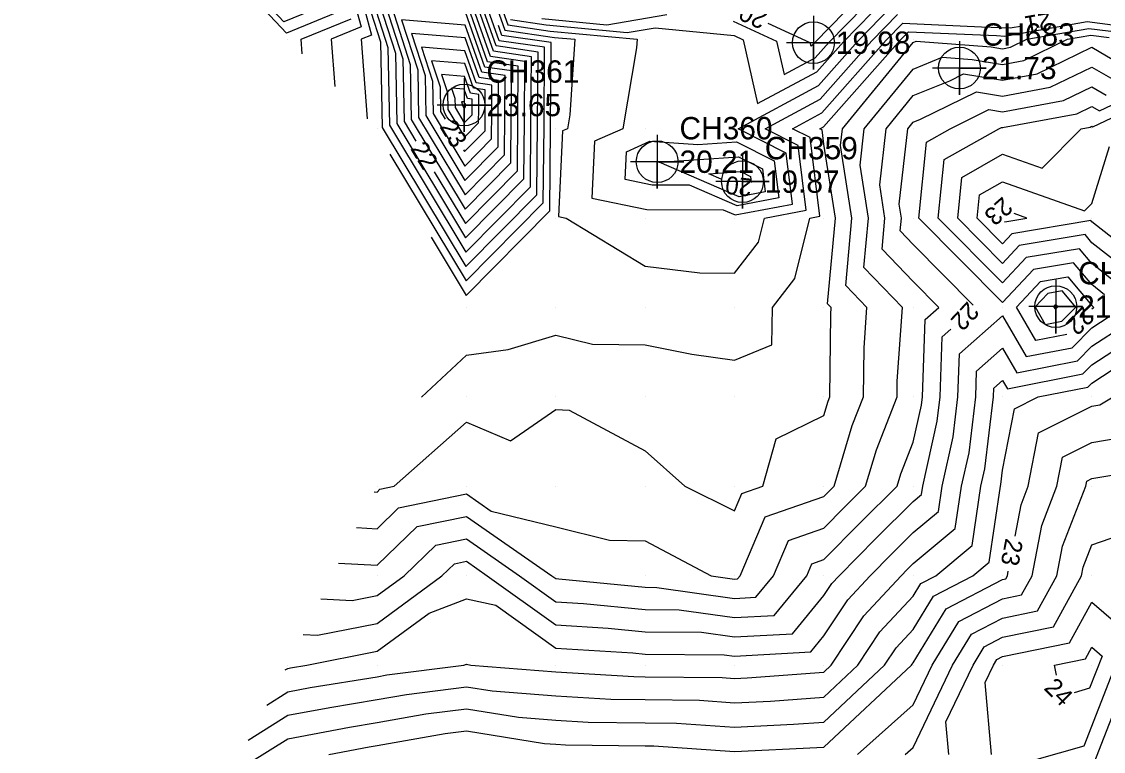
# Model space of a CAD drawing. Extents: x 2531902 to 2533249, y 715219 to 716099.
# Drawn here: x 2532680.2 to 2532801.3, y 715530.4 to 715612 of the extents above; entities that cross this region are included whole.
import ezdxf

# ---------------------------------------------------------------- set-up
doc = ezdxf.new("R2010")
doc.units = 0
for name, color, linetype in [('DTM Contours Major', 7, 'Continuous'), ('DTM Contours Major Text', 7, 'Continuous'), ('DTM Contours Minor', 7, 'Continuous'), ('Exist DTM QL2 LIDAR Elevation Point', 7, 'Continuous'), ('Exist DTM Regular Point CELL', 7, 'Continuous'), ('Exist DTM Regular Point Cogo Elevation', 7, 'Continuous'), ('Exist DTM Regular Point Cogo Number', 7, 'Continuous')]:
    doc.layers.add(name, color=color, linetype=linetype)

msp = doc.modelspace()

# ---------------------------------------------------------------- linework, layer by layer
at = {"layer": 'DTM Contours Major'}
for points in [[(2532732.26, 715615.31), (2532730.81, 715619.4), (2532730.83, 715620.41), (2532728.37, 715621.29), (2532719.99, 715622.47), (2532714.91, 715622.89), (2532715.92, 715619.72), (2532718.24, 715611.38), (2532714.85, 715610), (2532715.26, 715604.74)], [(2532763.74, 715611.81), (2532768.45, 715609.64), (2532768.53, 715609.28), (2532768.86, 715609.46), (2532769, 715609.63), (2532775.8, 715616.6), (2532779.22, 715616.44), (2532793.91, 715615.79), (2532798.21, 715616.54), (2532800.2, 715616.3), (2532801.37, 715617.07)], [(2532732.38, 715607.49), (2532729.92, 715614.46), (2532720.51, 715615.24), (2532722.88, 715607.82), (2532723.02, 715600.82), (2532724.35, 715598.61)], [(2532724.99, 715569.97), (2532730, 715574.66), (2532734.69, 715575.31), (2532740, 715576.89), (2532744.11, 715575.89), (2532750, 715575.81), (2532755.22, 715574.78), (2532760, 715574.1), (2532764.18, 715575.82), (2532764.27, 715580), (2532766.77, 715583.23), (2532768.45, 715590), (2532769.54, 715590.21), (2532768.47, 715599), (2532766.5, 715600), (2532769.79, 715601.76), (2532776.99, 715609.9), (2532778.85, 715611.81), (2532787.64, 715611.41), (2532790.86, 715611.27), (2532792.22, 715611.51)], [(2532726.07, 715587.86), (2532729.98, 715581.36), (2532739.34, 715590.82), (2532739.42, 715600.15), (2532739.49, 715609.63), (2532733.98, 715610.43), (2532733.59, 715611.54)], [(2532791.4, 715554.44), (2532792.07, 715557.93), (2532792.87, 715560), (2532794.03, 715565.97), (2532800, 715568.96), (2532800.89, 715569.11), (2532802.4, 715570), (2532808.71, 715572.49), (2532810, 715574.61), (2532812.18, 715570.69), (2532814.07, 715567.41), (2532813.4, 715561.93), (2532816.55, 715570.83), (2532817.98, 715572.95), (2532820.02, 715580.42), (2532822.99, 715583.27), (2532830.28, 715597.71), (2532833.72, 715604), (2532839.45, 715610.25), (2532839.5, 715610.3)], [(2532730.78, 715604.55), (2532729.81, 715607.29), (2532726.11, 715607.6), (2532727.05, 715604.68), (2532727.1, 715601.93), (2532727.62, 715601.06)], [(2532726.41, 715595.18), (2532729.89, 715589.4), (2532735.71, 715595.29), (2532735.77, 715601.09), (2532735.81, 715606.99), (2532732.38, 715607.49)], [(2532786.71, 715580.25), (2532780, 715587.06), (2532778.56, 715588.56), (2532778.69, 715590), (2532778.45, 715591.55), (2532779.4, 715600), (2532780, 715600.73), (2532780.81, 715601.06), (2532787.07, 715604.14), (2532790, 715603.66), (2532795.35, 715604.65), (2532800, 715606.9), (2532802.34, 715605.54)], [(2532729.68, 715597.63), (2532729.8, 715597.44), (2532732.09, 715599.75), (2532732.11, 715602.04), (2532732.12, 715604.36), (2532730.78, 715604.55)], [(2532757.15, 715594.95), (2532760.73, 715595.2), (2532761.79, 715594.66), (2532761.88, 715593.98)], [(2532758.5, 715594.37), (2532757.15, 715594.95)], [(2532790.25, 715589.59), (2532792.73, 715590), (2532791.3, 715590.5)], [(2532790.23, 715589.56), (2532790.25, 715589.59)], [(2532791.55, 715580.03), (2532794.26, 715582.92), (2532797.32, 715583.43), (2532800, 715580.22), (2532800.12, 715580.12), (2532800.23, 715580), (2532800.16, 715579.91), (2532800.01, 715579.82)], [(2532797.19, 715576.98), (2532793.72, 715576.3), (2532791.55, 715580.03)], [(2532711.72, 715543.44), (2532713.35, 715543.35), (2532720, 715544.66), (2532727.27, 715550), (2532728.66, 715551.34), (2532730, 715551.62), (2532732.33, 715550), (2532740, 715544.49), (2532745.86, 715544.14), (2532750, 715543.74), (2532756.33, 715543.67), (2532760, 715543.15), (2532766.48, 715543.52), (2532770, 715547.78), (2532770.88, 715549.12), (2532771.7, 715550), (2532775.82, 715554.18), (2532780, 715558.3), (2532780.93, 715559.07), (2532781.07, 715560), (2532782.7, 715567.3), (2532783.02, 715570), (2532783.26, 715576.74), (2532784.22, 715577.58)], [(2532714.59, 715530), (2532719.13, 715530.87), (2532720, 715531.01), (2532727.64, 715532.36), (2532730, 715532.66), (2532738.76, 715531.24), (2532740, 715531.15), (2532741.08, 715531.08), (2532750, 715530.98), (2532750.97, 715530.97), (2532760, 715530.33), (2532769.23, 715530.77), (2532770, 715530.83), (2532779.8, 715540), (2532779.88, 715540.12), (2532780, 715540.25), (2532783.7, 715546.3), (2532790, 715549.57), (2532790.36, 715549.64), (2532790.55, 715550), (2532790.65, 715550.51)], [(2532799.29, 715540.71), (2532800, 715542.02), (2532801.15, 715541.02), (2532799.74, 715537.41), (2532798, 715536.92)], [(2532796.03, 715538.87), (2532795.82, 715540), (2532799.29, 715540.71)]]:
    msp.add_lwpolyline(points, dxfattribs=at)
at = {"layer": 'DTM Contours Minor'}
for points in [[(2532680.23, 715639.75), (2532680.75, 715639.45), (2532713.17, 715623.21), (2532715.95, 715613.19), (2532709.85, 715610.7), (2532701.16, 715619.94), (2532698.66, 715621.23), (2532689.96, 715621.44), (2532684.17, 715629.76), (2532680.23, 715639.75)], [(2532681.39, 715638.49), (2532684.59, 715636.63), (2532712.42, 715622.69), (2532714.81, 715614.09), (2532709.57, 715611.95), (2532702.11, 715619.88), (2532697.57, 715622.24), (2532689.94, 715622.42), (2532684.85, 715629.72), (2532681.39, 715638.49)], [(2532721.42, 715597.16), (2532729.97, 715582.97), (2532738.61, 715591.71), (2532738.69, 715600.34), (2532738.75, 715609.11), (2532733.66, 715609.84), (2532730.1, 715619.93), (2532730.1, 715620.05), (2532729.81, 715620.15), (2532728.82, 715620.29), (2532716.03, 715621.36), (2532718.58, 715613.38), (2532719.39, 715610.48), (2532718.21, 715610), (2532718.89, 715601.11)], [(2532733.34, 715609.26), (2532729.98, 715618.76), (2532717.15, 715619.83), (2532720.39, 715609.71), (2532720.57, 715600.15), (2532729.95, 715584.58), (2532737.89, 715592.6), (2532737.96, 715600.53), (2532738.02, 715608.58), (2532733.34, 715609.26)], [(2532733.02, 715608.67), (2532729.96, 715617.32), (2532718.27, 715618.3), (2532721.22, 715609.08), (2532721.38, 715600.38), (2532729.93, 715586.18), (2532737.16, 715593.5), (2532737.23, 715600.72), (2532737.28, 715608.05), (2532733.02, 715608.67)], [(2532731.53, 715618.87), (2532734.3, 715611.02), (2532739.86, 715610.21), (2532742.13, 715610), (2532741.57, 715601.57), (2532741.3, 715600), (2532740.75, 715599.75), (2532740.32, 715590.18), (2532741.18, 715590), (2532750, 715584.62), (2532756.11, 715583.89), (2532760, 715583.83), (2532762.69, 715587.31), (2532763.36, 715590), (2532768.01, 715590.89), (2532767.13, 715598.14), (2532763.45, 715600), (2532769.6, 715603.3), (2532775.39, 715609.84), (2532778.24, 715612.76)], [(2532732.24, 715618.34), (2532734.63, 715611.61), (2532739.39, 715610.92), (2532749.1, 715610), (2532749.04, 715609.04), (2532747.49, 715600), (2532744.33, 715598.59), (2532744.05, 715592.25), (2532750.21, 715590.97), (2532758.72, 715590.93), (2532760.08, 715590.35), (2532766.49, 715591.57), (2532765.8, 715597.27), (2532760.4, 715600), (2532769.41, 715604.84), (2532773.79, 715609.79), (2532777.63, 715613.72)], [(2532732.7, 715608.08), (2532729.94, 715615.89), (2532719.39, 715616.77), (2532722.05, 715608.45), (2532722.2, 715600.6), (2532729.91, 715587.79), (2532736.44, 715594.39), (2532736.5, 715600.9), (2532736.54, 715607.52), (2532732.7, 715608.08)], [(2532759.85, 715612.03), (2532764.7, 715609.8), (2532765.56, 715606.05), (2532769.04, 715607.92), (2532770.6, 715609.68), (2532776.41, 715615.64)], [(2532734.95, 715612.2), (2532738.92, 715611.62), (2532748.01, 715610.76), (2532751.13, 715611.29), (2532759.97, 715610.41), (2532760.96, 715609.96), (2532762.58, 715602.81), (2532769.23, 715606.38), (2532772.2, 715609.73), (2532777.02, 715614.68)], [(2532732.06, 715606.9), (2532729.9, 715613.02), (2532721.63, 715613.72), (2532723.72, 715607.19), (2532723.83, 715601.04), (2532729.87, 715591.01), (2532734.99, 715596.18), (2532735.03, 715601.28), (2532735.07, 715606.47), (2532732.06, 715606.9)], [(2532711.62, 715608.38), (2532711.5, 715610), (2532717.1, 715612.29)], [(2532719.68, 715559.37), (2532720, 715559.35), (2532720.33, 715559.67), (2532721.93, 715560), (2532730, 715567.18), (2532734.92, 715565.08), (2532740, 715568.6), (2532741.49, 715568.51), (2532750, 715563.97), (2532754.44, 715560), (2532760, 715557.27), (2532760.82, 715559.18), (2532763.17, 715560), (2532764.67, 715565.33), (2532770, 715567.91), (2532770.48, 715569.52), (2532770.67, 715570), (2532770.78, 715579.22), (2532770.83, 715580), (2532770.42, 715580.42), (2532771.29, 715590), (2532770, 715598.27), (2532769.81, 715599.87), (2532769.56, 715600), (2532769.97, 715600.22), (2532778.59, 715609.95), (2532779.46, 715610.85), (2532789.32, 715610.41), (2532790.25, 715610.36), (2532799.46, 715611.98), (2532803.71, 715611.45)], [(2532731.74, 715606.31), (2532729.87, 715611.59), (2532722.75, 715612.19), (2532724.55, 715606.57), (2532724.65, 715601.26), (2532729.85, 715592.62), (2532734.26, 715597.07), (2532734.3, 715601.47), (2532734.33, 715605.94), (2532731.74, 715606.31)], [(2532738.45, 715612.32), (2532745.73, 715611.63), (2532752.43, 715612.77)], [(2532717.69, 715555.39), (2532720, 715555.26), (2532722.41, 715557.59), (2532730, 715559.16), (2532732.76, 715557.24), (2532740, 715555.46), (2532746.01, 715553.99), (2532750, 715553.92), (2532757.41, 715550), (2532760, 715549.63), (2532760.35, 715549.65), (2532760.63, 715550), (2532763.43, 715556.57), (2532770, 715558.85), (2532770.57, 715559.43), (2532771.15, 715560), (2532773.19, 715566.81), (2532774.43, 715570), (2532774.5, 715575.5), (2532774.82, 715580), (2532772.46, 715582.46), (2532773.14, 715590), (2532771.87, 715598.13), (2532772.08, 715600), (2532780, 715609.66), (2532780.34, 715609.79), (2532788.73, 715609.15), (2532790, 715608.95), (2532790.89, 715609.11), (2532792.72, 715610), (2532799.67, 715611.21), (2532804.29, 715610.65)], [(2532731.42, 715605.73), (2532729.85, 715610.16), (2532723.87, 715610.66), (2532725.38, 715605.94), (2532725.46, 715601.49), (2532729.84, 715594.22), (2532733.54, 715597.97), (2532733.57, 715601.66), (2532733.6, 715605.41), (2532731.42, 715605.73)], [(2532715.7, 715551.4), (2532720, 715551.17), (2532724.5, 715555.5), (2532730, 715556.64), (2532739.56, 715550), (2532740, 715549.68), (2532740.34, 715549.66), (2532750, 715548.72), (2532751.3, 715548.7), (2532760, 715547.47), (2532762.39, 715547.61), (2532764.37, 715550), (2532766.05, 715553.95), (2532770, 715555.32), (2532772.32, 715557.68), (2532774.68, 715560), (2532775.91, 715564.09), (2532778.2, 715570), (2532778.22, 715571.78), (2532778.8, 715580), (2532774.49, 715584.49), (2532774.99, 715590), (2532774.06, 715595.94), (2532774.52, 715600), (2532780, 715606.68), (2532783.24, 715607.99), (2532786.61, 715607.74), (2532790, 715607.18), (2532792.38, 715607.62), (2532797.28, 715610), (2532799.88, 715610.45), (2532801.92, 715610.2)], [(2532713.71, 715547.42), (2532717.23, 715547.23), (2532720, 715547.78), (2532723.03, 715550), (2532726.58, 715553.42), (2532730, 715554.13), (2532735.94, 715550), (2532740, 715547.09), (2532743.1, 715546.9), (2532750, 715546.23), (2532753.82, 715546.18), (2532760, 715545.31), (2532764.44, 715545.56), (2532768.1, 715550), (2532768.67, 715551.33), (2532770, 715551.8), (2532774.07, 715555.93), (2532778.21, 715560), (2532778.62, 715561.38), (2532780, 715564.94), (2532780.93, 715569.07), (2532781.04, 715570), (2532781.34, 715578.66), (2532782.86, 715580), (2532780, 715582.9), (2532776.53, 715586.53), (2532776.84, 715590), (2532776.26, 715593.74), (2532776.96, 715600), (2532780, 715603.71), (2532784.1, 715605.37), (2532785.65, 715606.13), (2532790, 715605.42), (2532793.86, 715606.14), (2532800, 715609.11), (2532803.09, 715607.31)], [(2532731.1, 715605.14), (2532729.83, 715608.72), (2532724.99, 715609.13), (2532726.21, 715605.31), (2532726.28, 715601.71), (2532729.82, 715595.83), (2532732.81, 715598.86), (2532732.84, 715601.85), (2532732.86, 715604.88), (2532731.1, 715605.14)], [(2532730.46, 715603.96), (2532729.79, 715605.86), (2532727.23, 715606.07), (2532727.88, 715604.05), (2532727.91, 715602.15), (2532729.78, 715599.05), (2532731.36, 715600.65), (2532731.38, 715602.22), (2532731.39, 715603.83), (2532730.46, 715603.96)], [(2532730.14, 715603.37), (2532729.77, 715604.42), (2532728.35, 715604.54), (2532728.71, 715603.42), (2532728.73, 715602.37), (2532729.76, 715600.66), (2532730.64, 715601.54), (2532730.65, 715602.41), (2532730.65, 715603.3), (2532730.14, 715603.37)], [(2532801.43, 715581.43), (2532800, 715582.56), (2532797.96, 715585), (2532793.46, 715584.25), (2532790, 715580.56), (2532780.63, 715590), (2532781.49, 715598.51), (2532784.13, 715600), (2532788.48, 715602.14), (2532790, 715601.89), (2532796.84, 715603.16), (2532800, 715604.69), (2532801.59, 715603.77)], [(2532802.74, 715582.74), (2532800, 715584.91), (2532798.61, 715586.58), (2532792.66, 715585.58), (2532790, 715582.75), (2532782.81, 715590), (2532783.46, 715596.54), (2532789.6, 715600), (2532789.9, 715600.15), (2532790, 715600.13), (2532798.32, 715601.68), (2532800, 715602.49), (2532800.84, 715602), (2532807.31, 715605.05)], [(2532804.05, 715584.05), (2532800, 715587.25), (2532799.25, 715588.15), (2532791.86, 715586.92), (2532790, 715584.94), (2532784.98, 715590), (2532785.44, 715594.56), (2532790, 715597.14), (2532794.42, 715595.58), (2532798.8, 715600), (2532799.81, 715600.19), (2532800, 715600.28), (2532800.1, 715600.23), (2532807.91, 715603.92)], [(2532729.82, 715602.79), (2532729.74, 715602.99), (2532729.47, 715603.01), (2532729.54, 715602.8), (2532729.55, 715602.59), (2532729.74, 715602.26), (2532729.91, 715602.43), (2532729.91, 715602.6), (2532729.91, 715602.77), (2532729.82, 715602.79)], [(2532760.22, 715598.55), (2532764.46, 715596.4), (2532764.97, 715592.26), (2532760.3, 715591.36), (2532754.96, 715593.68), (2532750.79, 715593.7), (2532747.77, 715594.32), (2532747.91, 715597.43), (2532750.52, 715598.59), (2532755.89, 715598.25), (2532760.22, 715598.55)], [(2532805.36, 715585.36), (2532800, 715589.6), (2532799.89, 715589.73), (2532791.05, 715588.25), (2532790, 715587.13), (2532787.15, 715590), (2532787.41, 715592.59), (2532790, 715594.05), (2532799.18, 715590.82), (2532800, 715591.64), (2532801.98, 715598.02)], [(2532751.57, 715596.26), (2532760.47, 715596.87), (2532763.13, 715595.53), (2532763.44, 715592.94), (2532760.52, 715592.38), (2532751.57, 715596.26)], [(2532798.19, 715580.04), (2532796.68, 715581.85), (2532795.07, 715581.58), (2532793.64, 715580.06), (2532794.78, 715578.1), (2532796.62, 715578.46), (2532798.19, 715580.04)], [(2532796.19, 715580.09), (2532796.04, 715580.28), (2532795.87, 715580.25), (2532795.72, 715580.1), (2532795.84, 715579.89), (2532796.03, 715579.93), (2532796.19, 715580.09)], [(2532707.65, 715535.54), (2532710, 715537.01), (2532712.51, 715537.49), (2532720, 715538.71), (2532721.1, 715538.9), (2532729.72, 715540), (2532730, 715540.11), (2532730.51, 715540), (2532740, 715539.26), (2532748.73, 715538.73), (2532750, 715538.71), (2532758.62, 715538.62), (2532760, 715538.52), (2532761.41, 715538.59), (2532770, 715539.22), (2532770.84, 715540), (2532774.48, 715545.52), (2532778.64, 715550), (2532779.32, 715550.68), (2532780, 715551.36), (2532784.71, 715555.29), (2532785.41, 715560), (2532786.25, 715563.75), (2532787, 715570), (2532787.1, 715572.9), (2532790, 715575.46), (2532791.6, 715572.71), (2532798.38, 715574.04), (2532800, 715575.67), (2532803.67, 715578.07)], [(2532709.72, 715539.47), (2532710, 715539.64), (2532710.3, 715539.7), (2532712.15, 715540), (2532720, 715541.55), (2532725.82, 715545.82), (2532730, 715547.4), (2532733.29, 715546.71), (2532740, 715541.89), (2532748.62, 715541.38), (2532750, 715541.24), (2532758.85, 715541.15), (2532760, 715540.99), (2532768.53, 715541.47), (2532770, 715543.26), (2532772.68, 715547.32), (2532775.17, 715550), (2532777.57, 715552.43), (2532780, 715554.83), (2532782.82, 715557.18), (2532783.24, 715560), (2532784.48, 715565.52), (2532785.01, 715570), (2532785.18, 715574.82), (2532790, 715579.08), (2532792.66, 715574.51), (2532797.8, 715575.51), (2532800, 715577.74), (2532801.92, 715578.99)], [(2532705.58, 715531.61), (2532710, 715534.39), (2532714.72, 715535.28), (2532720, 715536.14), (2532723.28, 715536.72), (2532730, 715537.58), (2532732.89, 715537.11), (2532740, 715536.56), (2532746.18, 715536.18), (2532750, 715536.14), (2532756.07, 715536.07), (2532760, 715535.79), (2532764.02, 715535.98), (2532770, 715536.42), (2532773.82, 715540), (2532776.28, 715543.72), (2532780, 715547.73), (2532780.86, 715549.14), (2532782.53, 715550), (2532786.6, 715553.4), (2532787.59, 715560), (2532788.03, 715561.97), (2532788.99, 715570), (2532789.02, 715570.98), (2532790, 715571.84), (2532790.54, 715570.91), (2532798.97, 715572.57), (2532800, 715573.6), (2532805.43, 715577.15)], [(2532703.5, 715527.68), (2532710, 715531.76), (2532716.93, 715533.07), (2532720, 715533.57), (2532725.46, 715534.54), (2532730, 715535.12), (2532735.82, 715534.18), (2532740, 715533.85), (2532743.63, 715533.63), (2532750, 715533.56), (2532753.52, 715533.52), (2532760, 715533.06), (2532766.62, 715533.38), (2532770, 715533.62), (2532776.81, 715540), (2532778.08, 715541.92), (2532780, 715543.99), (2532782.28, 715547.72), (2532786.68, 715550), (2532788.49, 715551.51), (2532789.76, 715560), (2532789.81, 715560.19), (2532790, 715561.82), (2532791.33, 715568.67), (2532793.98, 715570), (2532799.56, 715571.09), (2532800, 715571.54), (2532804.65, 715574.58)], [(2532773.77, 715530), (2532780, 715535.55), (2532782.13, 715540), (2532785.12, 715544.88), (2532790, 715547.42), (2532792.14, 715547.86), (2532793.32, 715550), (2532794.39, 715555.61), (2532796.09, 715560), (2532796.72, 715563.28), (2532800, 715564.91), (2532804.36, 715565.64)], [(2532779.12, 715530), (2532780, 715530.79), (2532784.42, 715540), (2532786.53, 715543.47), (2532790, 715545.26), (2532793.93, 715546.07), (2532796.08, 715550), (2532796.71, 715553.29), (2532799.31, 715560), (2532799.42, 715560.58), (2532800, 715560.86), (2532807.82, 715562.18)], [(2532783.98, 715530), (2532783.66, 715533.66), (2532786.7, 715540), (2532787.95, 715542.05), (2532790, 715543.11), (2532795.71, 715544.29), (2532798.85, 715550), (2532799.03, 715550.97), (2532800, 715553.47), (2532805.29, 715555.29), (2532803.26, 715549.28), (2532806.88, 715546.15), (2532798.44, 715524.46)], [(2532788.75, 715530), (2532788.05, 715538.05), (2532788.99, 715540), (2532789.37, 715540.63), (2532790, 715540.95), (2532797.5, 715542.5), (2532800, 715547.06), (2532804.01, 715543.59), (2532799.09, 715530.94), (2532791.09, 715528.66)]]:
    msp.add_lwpolyline(points, dxfattribs=at)
at = {"layer": 'Exist DTM QL2 LIDAR Elevation Point'}
for p, q in [((2532710, 715610), (2532710, 715610)), ((2532720, 715610), (2532720, 715610)), ((2532730, 715610), (2532730, 715610)), ((2532740, 715610), (2532740, 715610)), ((2532750, 715610), (2532750, 715610)), ((2532760, 715610), (2532760, 715610)), ((2532780, 715610), (2532780, 715610)), ((2532790, 715610), (2532790, 715610)), ((2532800, 715610), (2532800, 715610)), ((2532720, 715600), (2532720, 715600)), ((2532740, 715600), (2532740, 715600)), ((2532750, 715600), (2532750, 715600)), ((2532760, 715600), (2532760, 715600)), ((2532770, 715600), (2532770, 715600)), ((2532780, 715600), (2532780, 715600)), ((2532790, 715600), (2532790, 715600)), ((2532800, 715600), (2532800, 715600)), ((2532740, 715590), (2532740, 715590)), ((2532750, 715590), (2532750, 715590)), ((2532760, 715590), (2532760, 715590)), ((2532770, 715590), (2532770, 715590)), ((2532780, 715590), (2532780, 715590)), ((2532790, 715590), (2532790, 715590)), ((2532800, 715590), (2532800, 715590)), ((2532730, 715580), (2532730, 715580)), ((2532740, 715580), (2532740, 715580)), ((2532750, 715580), (2532750, 715580)), ((2532760, 715580), (2532760, 715580)), ((2532770, 715580), (2532770, 715580)), ((2532780, 715580), (2532780, 715580)), ((2532790, 715580), (2532790, 715580)), ((2532800, 715580), (2532800, 715580)), ((2532730, 715570), (2532730, 715570)), ((2532740, 715570), (2532740, 715570)), ((2532750, 715570), (2532750, 715570)), ((2532760, 715570), (2532760, 715570)), ((2532770, 715570), (2532770, 715570)), ((2532780, 715570), (2532780, 715570)), ((2532790, 715570), (2532790, 715570)), ((2532800, 715570), (2532800, 715570)), ((2532720, 715560), (2532720, 715560)), ((2532730, 715560), (2532730, 715560)), ((2532740, 715560), (2532740, 715560)), ((2532750, 715560), (2532750, 715560)), ((2532760, 715560), (2532760, 715560)), ((2532770, 715560), (2532770, 715560)), ((2532780, 715560), (2532780, 715560)), ((2532790, 715560), (2532790, 715560)), ((2532800, 715560), (2532800, 715560)), ((2532720, 715550), (2532720, 715550)), ((2532730, 715550), (2532730, 715550)), ((2532740, 715550), (2532740, 715550)), ((2532750, 715550), (2532750, 715550)), ((2532760, 715550), (2532760, 715550)), ((2532770, 715550), (2532770, 715550)), ((2532780, 715550), (2532780, 715550)), ((2532790, 715550), (2532790, 715550)), ((2532800, 715550), (2532800, 715550)), ((2532710, 715540), (2532710, 715540)), ((2532720, 715540), (2532720, 715540)), ((2532730, 715540), (2532730, 715540)), ((2532740, 715540), (2532740, 715540)), ((2532750, 715540), (2532750, 715540)), ((2532760, 715540), (2532760, 715540)), ((2532770, 715540), (2532770, 715540)), ((2532780, 715540), (2532780, 715540)), ((2532790, 715540), (2532790, 715540)), ((2532800, 715540), (2532800, 715540))]:
    msp.add_line(p, q, dxfattribs=at)
at = {"layer": 'Exist DTM Regular Point CELL'}
for points in [[(2532768.84, 715612.62), (2532768.84, 715606.62), (2532768.84, 715609.62), (2532771.84, 715609.62), (2532765.84, 715609.62)], [(2532785.18, 715609.79), (2532785.18, 715603.79), (2532785.18, 715606.79), (2532788.18, 715606.79), (2532782.18, 715606.79)], [(2532729.74, 715605.65), (2532729.74, 715599.65), (2532729.74, 715602.65), (2532732.74, 715602.65), (2532726.74, 715602.65)], [(2532751.35, 715599.31), (2532751.35, 715593.31), (2532751.35, 715596.31), (2532754.35, 715596.31), (2532748.35, 715596.31)], [(2532760.9, 715597.08), (2532760.9, 715591.08), (2532760.9, 715594.08), (2532763.9, 715594.08), (2532757.9, 715594.08)], [(2532795.96, 715583.1), (2532795.96, 715577.1), (2532795.96, 715580.1), (2532798.96, 715580.1), (2532792.96, 715580.1)]]:
    msp.add_lwpolyline(points, dxfattribs=at)
for centre in [(2532768.84, 715609.62), (2532785.18, 715606.79), (2532729.74, 715602.65), (2532751.35, 715596.31), (2532760.9, 715594.08), (2532795.96, 715580.1)]:
    msp.add_circle(centre, 2.34, dxfattribs=at)

# ---------------------------------------------------------------- texts
at = {"layer": 'DTM Contours Major Text'}
for s, rotation, p in [('20', 155.2492, (2532763.83, 715612.87)), ('21', 189.9212, (2532795.29, 715613.06)), ('23', 301.0538, (2532726.95, 715600.23)), ('22', 301.0538, (2532723.68, 715597.78)), ('20', 173.3374, (2532762.07, 715594.38)), ('23', 221.1829, (2532790.03, 715592.48)), ('22', 226.9498, (2532786.1, 715580.78)), ('22', 225.1163, (2532799.05, 715580.26)), ('23', 259.1987, (2532790.35, 715554.26)), ('24', 315.1013, (2532794.54, 715537.35))]:
    msp.add_text(s, height=2, rotation=rotation, dxfattribs=at).set_placement(p)
at = {"layer": 'Exist DTM Regular Point Cogo Elevation'}
for s, p in [('19.98', (2532771.34, 715608.37)), ('21.73', (2532787.68, 715605.54)), ('23.65', (2532732.24, 715601.4)), ('20.21', (2532753.85, 715595.06)), ('19.87', (2532763.4, 715592.83)), ('21.58', (2532798.46, 715578.85))]:
    msp.add_text(s, height=2.5, dxfattribs=at).set_placement(p)
at = {"layer": 'Exist DTM Regular Point Cogo Number'}
for s, p in [('CH683', (2532787.68, 715609.29)), ('CH361', (2532732.24, 715605.15)), ('CH360', (2532753.85, 715598.81)), ('CH359', (2532763.4, 715596.58)), ('CH358', (2532798.46, 715582.6))]:
    msp.add_text(s, height=2.5, dxfattribs=at).set_placement(p)

doc.saveas('drawing.dxf')
